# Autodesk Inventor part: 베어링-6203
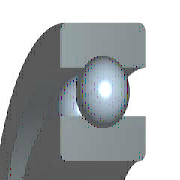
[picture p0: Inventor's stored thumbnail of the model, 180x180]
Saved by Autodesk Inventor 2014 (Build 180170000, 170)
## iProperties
IsCustomPart: 0
Created: 2016-05
Part Number: 베어링-6203
Material: 강, 연강
Description: 깊은 그루브 볼 베어링
Document SubType Name: Modeling
Standard: KS B 2023
Designer: mduedu
Standards Organization: KS
Language: ko-KR
Size Designation: 6203 - 17 x 40 x 12
Categories: <MemberInstance><Categories><Category DisplayName="샤프트 부품" InternalName="7f7aeb1f-a693-4053-b835-cee3144e0d98" Mnemonic="SHFT"><Category DisplayName="베어링" Inter
Density: 1 g/cm^3
Appearance: 노란색
Author: mduedu
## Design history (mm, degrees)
sketch "스케치" dims "d0" = 5.98 (= -0.26 x WD + 0.26 x BD)
  geometry: L1 (3.01, 14.25)-(8.99, 14.25); L2 (6, 14.25)-(6, 11.26); L3 (6, 14.25)-(6, 17.24); L4 (3.778, 12.249)-(0, 12.249); L5 (0, 8.5)-(12, 8.5); L6 (3.778, 16.251)-(0, 16.251); L7 (0, 20)-(12, 20); L8 (12, 8.5)-(12, 12.249); L9 (8.222, 12.249)-(12, 12.249); L10 (8.222, 16.251)-(12, 16.251); L11 (12, 20)-(12, 16.251); L12 (-1.4, 0)-(8.4, 0) reference; L13 (0, -0.3)-(0, 5.3) reference
  constraints: 22 end point, 4 point on line, 2 collinear, 2 perpendicular, 2 symmetric about line, 1 midpoint, 1 parallel, 14 other
  dimensions: "d9" = 17 diameter of L5 L12 (= WD); "d11" = 40 diameter of L7 L12 (= BD); "d12" = 12 distance between parallel lines of L8 L13 (= KB); "d13" = 24.498 diameter of L9 L12 (= 0.326 x BD + 0.674 x WD)
revolve "본체" stored, may be unused: angle "d6" = 90 deg
revolve "볼" stored, may be unused: angle "d7" = 90 deg
pattern_circular "IDS_ARRAYBALL[SIMPL:T]" dims angle "d3" = 360 deg
body "Solid1"
fillet "모깎기1" dims "d1" = 0.6 (= KRS)
other parameters: "WD" = 17 [user parameter; used in 5 equation terms], "BD" = 40 [user parameter; used in 5 equation terms], "KB" = 12 [user parameter; used in 1 equation term], "KRS" = 0.6 [user parameter; used in 1 equation term], "d4" = 0, "d5" = 0, "d8" = 0, "d14" = 0, "d15" = 0, "BBA" = 0 [user parameter], "BC0" = 4750000 [user parameter], "BC" = 9560000 [user parameter], "WR" = 8.5 (= 0.5 x WD) [user parameter]
